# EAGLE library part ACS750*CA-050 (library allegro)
Current Sensor display layer 49 Reference in BRD and place VIAs on circles Source: www.allegromicro.com/datafile/0750-050.pdf
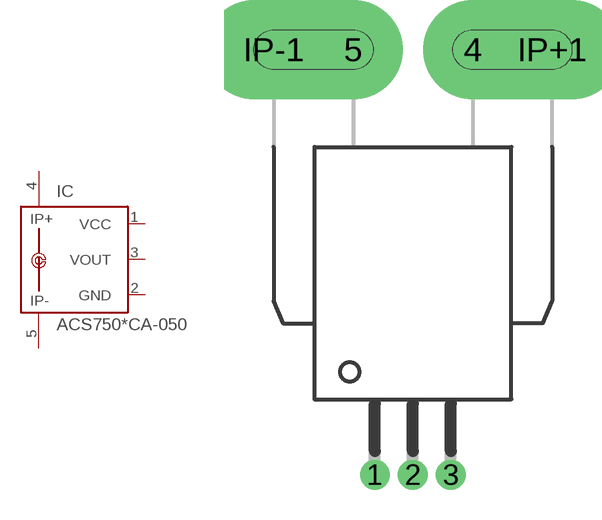
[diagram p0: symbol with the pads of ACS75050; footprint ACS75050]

Designator prefix IC

## ACS750LCA-050 (MF: ALLEGRO MICROSYSTEMS, INC.; MPN: ACS750LCA-050; OC_FARNELL: 1457176; OC_NEWARK: 61H4464), ACS750SCA-050 (MF: ALLEGRO MICROSYSTEMS, INC.; MPN: ACS750SCA-050; OC_FARNELL: 1457175; OC_NEWARK: 81H6588)  [ACS75050]
1  VCC  pwr
2  GND  pwr
3  VOUT  out
4  IP+  pas
5  IP-  pas
IP+1  IP+1  in
IP-1  IP-1  in

## Footprint ACS75050 (pad centres in mm)
Current Sensor In BRD, display layer 49 Reference and place VIAs with drill = 0,5mm on circles In DRC, set Clearance same signals PAD to VIA = 0 Source: www.allegromicro.com/datafile/0750-050.pdf
drill 0.8 pad 1.5 round: 1 -1.91,-21.4; 2 0,-21.4; 3 1.91,-21.4
drill 2 pad 5 offset: 4 3,0; 5 -3,0
drill 2 pad 4 offset: IP+1 7,0; IP-1 -7,0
